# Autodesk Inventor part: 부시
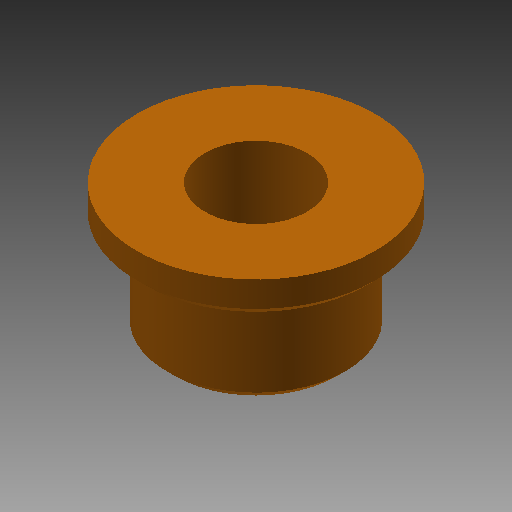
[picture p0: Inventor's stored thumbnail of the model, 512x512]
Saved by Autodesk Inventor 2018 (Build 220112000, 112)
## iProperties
Created: 2016-02
Part Number: 부시
Material: 강철, 연강
Document SubType Name: Modeling
Designer: test
Density: 1 g/cm^3
Appearance: 주황색
Author: test
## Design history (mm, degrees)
sketch "스케치1"
  geometry: C1 r 14 at (0, 0); C2 r 10.5 at (0, 0); 1 further point
  constraints: 2 centre point, 2 coincident
  dimensions: "d0" = 28 diameter of C1; "d1" = 21 diameter of C2
extrude "돌출1" new body sketch "스케치1" distance "d2" = 4; taper "d3" = 0 deg
extrude "돌출2" join sketch "스케치1" distance "d4" = 11; taper "d5" = 0 deg
hole "구멍1" diameter "d8" = 12; stored, may be unused: countersink angle "d12" = 90 deg, drill point angle "d14" = 118 deg; dims "d6" = 10, "d7" = 10, "d9" = 6, "d10" = 4, "d11" = 2, "d13" = 8
chamfer "모따기1" distance "d15" = 1; stored, may be unused: second distance "d16" = 2, angle "d17" = 45 deg
chamfer "모따기2" distance "d18" = 1; stored, may be unused: second distance "d19" = 2, angle "d20" = 45 deg
node "솔리드1"
